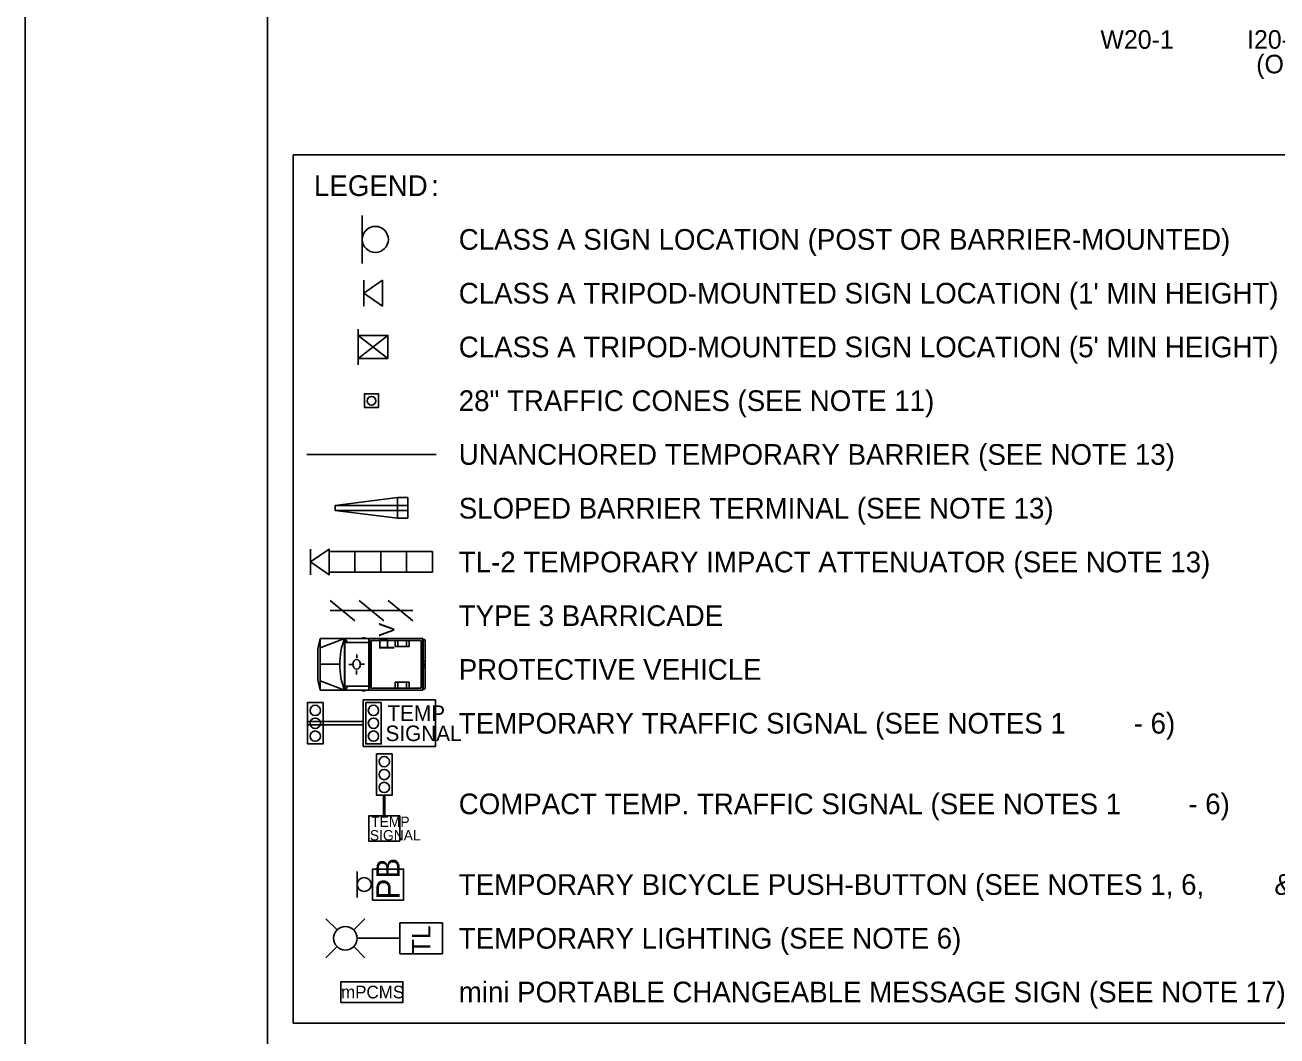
# Model space of a CAD drawing. Extents: x 99976 to 100136, y 99905 to 100011.
# Drawn here: x 99999.062 to 100003.905, y 99911.176 to 99915.088 of the extents above; entities that cross this region are included whole.
import ezdxf

# ---------------------------------------------------------------- set-up
doc = ezdxf.new("R2010")
doc.units = 0
for name, color, linetype in [('SH_GI_PlotLimits', 7, 'Continuous'), ('SH_GI_SheetBorder', 7, 'Continuous'), ('TR_SN_ConstructionSigns', 7, 'Continuous'), ('TR_WZ_BarricadeType3', 7, 'Continuous'), ('TR_WZ_BarrierTemp', 7, 'Continuous'), ('TR_WZ_PortableChangeMessageSign', 7, 'Continuous'), ('TR_WZ_PortableLightStandard', 7, 'Continuous'), ('TR_WZ_PortableSignMount5ftMinBlk-Wht', 7, 'Continuous'), ('TR_WZ_PortableSignMountBlk-Wht', 7, 'Continuous'), ('TR_WZ_ProtectiveVehicle', 7, 'Continuous'), ('TR_WZ_ScaleTerminalEndSection', 7, 'Continuous'), ('TR_WZ_Sign', 7, 'Continuous'), ('TR_WZ_TempSignal', 7, 'Continuous'), ('TR_WZ_TrafficCone', 7, 'Continuous'), ('TR_WZ_WorkZoneDetails', 7, 'Continuous'), ('TR_WZ_WorkZoneTextCurrent', 7, 'Continuous')]:
    doc.layers.add(name, color=color, linetype=linetype)

msp = doc.modelspace()

# ---------------------------------------------------------------- linework, layer by layer
at = {"layer": 'SH_GI_PlotLimits'}
msp.add_lwpolyline([(99999.0625, 99909.6875), (100016.0625, 99909.6875), (100016.0625, 99920.6875), (99999.0625, 99920.6875)], close=True, dxfattribs=at)
at = {"layer": 'SH_GI_SheetBorder'}
msp.add_line((100000, 99920.375), (100000, 99910), dxfattribs=at)
at = {"layer": 'TR_WZ_BarricadeType3'}
for p, q in [((100000.3381, 99912.7823), (100000.2425, 99912.8615)), ((100000.4503, 99912.7823), (100000.3547, 99912.8615)), ((100000.5625, 99912.7823), (100000.4669, 99912.8615)), ((100000.2425, 99912.8219), (100000.5625, 99912.8219))]:
    msp.add_line(p, q, dxfattribs=at)
at = {"layer": 'TR_WZ_BarrierTemp'}
msp.add_line((100000.1525, 99913.4259), (100000.6525, 99913.4259), dxfattribs=at)
at = {"layer": 'TR_WZ_PortableChangeMessageSign'}
msp.add_lwpolyline([(100000.2841, 99911.3059), (100000.5241, 99911.3059), (100000.5241, 99911.3859), (100000.2841, 99911.3859)], close=True, dxfattribs=at)
msp.add_lwpolyline([(100000.2841, 99911.3059), (100000.5241, 99911.3059), (100000.5241, 99911.3859), (100000.2841, 99911.3859), (100000.2841, 99911.3059)], dxfattribs=at)
at = {"layer": 'TR_WZ_PortableLightStandard'}
for p, q in [((100000.2692, 99911.5863), (100000.2261, 99911.6293)), ((100000.3339, 99911.5863), (100000.377, 99911.6293)), ((100000.6777, 99911.6139), (100000.5117, 99911.6139)), ((100000.5117, 99911.6139), (100000.5117, 99911.4939)), ((100000.6777, 99911.6139), (100000.5117, 99911.6139)), ((100000.6777, 99911.6139), (100000.6777, 99911.4939)), ((100000.5117, 99911.5539), (100000.3473, 99911.5539)), ((100000.2692, 99911.5215), (100000.2261, 99911.4784)), ((100000.3339, 99911.5215), (100000.377, 99911.4784)), ((100000.6777, 99911.4939), (100000.5117, 99911.4939)), ((100000.5117, 99911.4939), (100000.6777, 99911.4939))]:
    msp.add_line(p, q, dxfattribs=at)
for points in [[(100000.5117, 99911.6139), (100000.5117, 99911.5539), (100000.5117, 99911.4939)], [(100000.6777, 99911.4939), (100000.6777, 99911.5539), (100000.6777, 99911.6139)]]:
    msp.add_lwpolyline(points, dxfattribs=at)
msp.add_circle((100000.3015, 99911.5539), 0.0457, dxfattribs=at)
msp.add_circle((100000.3015, 99911.5539), 0.0457, dxfattribs=at)
at = {"layer": 'TR_WZ_PortableSignMount5ftMinBlk-Wht'}
for p, q in [((100000.3512, 99913.9109), (100000.3512, 99913.7729)), ((100000.4663, 99913.7971), (100000.3512, 99913.8867)), ((100000.4663, 99913.8867), (100000.3512, 99913.7971)), ((100000.4088, 99913.8419), (100000.4088, 99913.8419)), ((100000.4089, 99913.8418), (100000.4089, 99913.8418))]:
    msp.add_line(p, q, dxfattribs=at)
msp.add_lwpolyline([(100000.4663, 99913.7971), (100000.4663, 99913.8867), (100000.3512, 99913.8867), (100000.3512, 99913.7971)], close=True, dxfattribs=at)
at = {"layer": 'TR_WZ_PortableSignMountBlk-Wht'}
for p, q in [((100000.3728, 99913.9999), (100000.3728, 99914.0999)), ((100000.1667, 99913.0599), (100000.1667, 99912.9599))]:
    msp.add_line(p, q, dxfattribs=at)
for points in [[(100000.3728, 99914.0498), (100000.4447, 99914.0999), (100000.4447, 99913.9999)], [(100000.1667, 99913.01), (100000.2385, 99912.9599), (100000.2385, 99913.0599)]]:
    msp.add_lwpolyline(points, close=True, dxfattribs=at)
at = {"layer": 'TR_WZ_ProtectiveVehicle'}
for p, q in [((100000.2036, 99912.7139), (100000.1944, 99912.6735)), ((100000.2036, 99912.5139), (100000.2036, 99912.7139)), ((100000.2036, 99912.7139), (100000.3925, 99912.7139)), ((100000.2036, 99912.6773), (100000.2981, 99912.7139)), ((100000.2981, 99912.5139), (100000.2981, 99912.7139)), ((100000.2998, 99912.5139), (100000.2998, 99912.7139)), ((100000.3098, 99912.6984), (100000.2998, 99912.7139)), ((100000.2998, 99912.6984), (100000.3925, 99912.6984)), ((100000.3668, 99912.7167), (100000.3781, 99912.7167)), ((100000.3925, 99912.5139), (100000.3925, 99912.7139)), ((100000.601, 99912.7139), (100000.3953, 99912.7139)), ((100000.3953, 99912.5139), (100000.3953, 99912.7139)), ((100000.5952, 99912.7059), (100000.4011, 99912.7059)), ((100000.4011, 99912.5219), (100000.4011, 99912.7059)), ((100000.4938, 99912.7059), (100000.4938, 99912.6829)), ((100000.5038, 99912.7059), (100000.5038, 99912.6829)), ((100000.5378, 99912.7059), (100000.5378, 99912.6829)), ((100000.5488, 99912.7059), (100000.5488, 99912.6829)), ((100000.5952, 99912.5219), (100000.5952, 99912.7059)), ((100000.601, 99912.5139), (100000.601, 99912.7139)), ((100000.6061, 99912.7106), (100000.6017, 99912.7106)), ((100000.6017, 99912.5172), (100000.6017, 99912.7106)), ((100000.6106, 99912.5233), (100000.6106, 99912.7045)), ((100000.1944, 99912.5543), (100000.1944, 99912.6735)), ((100000.3458, 99912.6524), (100000.3455, 99912.6373)), ((100000.5488, 99912.6829), (100000.4938, 99912.6829)), ((100000.2036, 99912.6139), (100000.2795, 99912.6139)), ((100000.315, 99912.6138), (100000.3276, 99912.6138)), ((100000.3592, 99912.6142), (100000.3592, 99912.6142)), ((100000.376, 99912.6147), (100000.3611, 99912.6143)), ((100000.6106, 99912.628), (100000.6017, 99912.6242)), ((100000.6106, 99912.5998), (100000.6017, 99912.6036)), ((100000.6082, 99912.6139), (100000.6041, 99912.6139)), ((100000.6061, 99912.6111), (100000.6061, 99912.6167)), ((100000.2036, 99912.5139), (100000.1944, 99912.5543)), ((100000.2036, 99912.5505), (100000.2981, 99912.5139)), ((100000.3451, 99912.5743), (100000.3451, 99912.5904)), ((100000.2036, 99912.5139), (100000.3925, 99912.5139)), ((100000.2998, 99912.5139), (100000.3118, 99912.5294)), ((100000.2998, 99912.5294), (100000.3925, 99912.5294)), ((100000.3668, 99912.5111), (100000.3781, 99912.5111)), ((100000.601, 99912.5139), (100000.3953, 99912.5139)), ((100000.5952, 99912.5219), (100000.4011, 99912.5219)), ((100000.5488, 99912.5449), (100000.4938, 99912.5449)), ((100000.4938, 99912.5219), (100000.4938, 99912.5449)), ((100000.5038, 99912.5219), (100000.5038, 99912.5449)), ((100000.5378, 99912.5219), (100000.5378, 99912.5449)), ((100000.5488, 99912.5219), (100000.5488, 99912.5449)), ((100000.6061, 99912.5172), (100000.6017, 99912.5172))]:
    msp.add_line(p, q, dxfattribs=at)
for centre, major_axis, start_param, end_param in [((100000.4331, 99912.6139), (0, -0.2099), 4.215852, 5.209111), ((100000.6061, 99912.7045), (0, 0.0061), 4.712389, 6.283185), ((100000.6061, 99912.5233), (0, -0.0061), 6.283185, 7.853982)]:
    msp.add_ellipse(centre, major_axis=major_axis, ratio=0.73155, start_param=start_param, end_param=end_param, dxfattribs=at)
for centre, major_axis in [((100000.3451, 99912.6139), (0, 0.0193)), ((100000.6061, 99912.6139), (0, 0.00282))]:
    msp.add_ellipse(centre, major_axis=major_axis, ratio=0.73155, dxfattribs=at)
at = {"layer": 'TR_WZ_ScaleTerminalEndSection'}
for p, q in [((100000.5025, 99913.259), (100000.2625, 99913.229)), ((100000.2625, 99913.229), (100000.5425, 99913.229)), ((100000.2625, 99913.229), (100000.2625, 99913.209)), ((100000.5025, 99913.259), (100000.5025, 99913.179)), ((100000.5425, 99913.259), (100000.5025, 99913.259)), ((100000.5425, 99913.259), (100000.5425, 99913.179)), ((100000.2625, 99913.209), (100000.5425, 99913.209)), ((100000.5025, 99913.179), (100000.2625, 99913.209)), ((100000.5425, 99913.179), (100000.5025, 99913.179))]:
    msp.add_line(p, q, dxfattribs=at)
at = {"layer": 'TR_WZ_Sign'}
for p, q in [((100000.3668, 99914.1647), (100000.3668, 99914.3511)), ((100000.3474, 99911.7119), (100000.3474, 99911.8119))]:
    msp.add_line(p, q, dxfattribs=at)
for centre, radius in [((100000.4172, 99914.258), 0.0504), ((100000.4172, 99914.258), 0.0504), ((100000.3744, 99911.762), 0.027), ((100000.3744, 99911.762), 0.027)]:
    msp.add_circle(centre, radius, dxfattribs=at)
at = {"layer": 'TR_WZ_TempSignal'}
for p, q in [((100000.215, 99912.4658), (100000.1551, 99912.4658)), ((100000.1551, 99912.4658), (100000.1551, 99912.306)), ((100000.215, 99912.306), (100000.215, 99912.4658)), ((100000.3701, 99912.4759), (100000.6501, 99912.4759)), ((100000.3701, 99912.2959), (100000.3701, 99912.4759)), ((100000.6501, 99912.4759), (100000.3701, 99912.4759)), ((100000.3701, 99912.4759), (100000.3701, 99912.3926)), ((100000.44, 99912.4658), (100000.3801, 99912.4658)), ((100000.3801, 99912.4658), (100000.3801, 99912.306)), ((100000.44, 99912.306), (100000.44, 99912.4658)), ((100000.6501, 99912.4759), (100000.6501, 99912.2959)), ((100000.6501, 99912.2959), (100000.6501, 99912.4759)), ((100000.3701, 99912.3926), (100000.1551, 99912.3926)), ((100000.1551, 99912.3926), (100000.1551, 99912.3792)), ((100000.1551, 99912.3792), (100000.3701, 99912.3792)), ((100000.3701, 99912.3792), (100000.3701, 99912.3926)), ((100000.3701, 99912.3926), (100000.3701, 99912.3792)), ((100000.3701, 99912.3792), (100000.3701, 99912.2959)), ((100000.1551, 99912.306), (100000.215, 99912.306)), ((100000.6501, 99912.2959), (100000.3701, 99912.2959)), ((100000.3701, 99912.2959), (100000.6501, 99912.2959)), ((100000.3801, 99912.306), (100000.44, 99912.306)), ((100000.4819, 99912.2672), (100000.422, 99912.2672)), ((100000.422, 99912.2672), (100000.422, 99912.1075)), ((100000.4819, 99912.1075), (100000.4819, 99912.2672)), ((100000.422, 99912.1075), (100000.4819, 99912.1075)), ((100000.5119, 99912.0275), (100000.3919, 99912.0275)), ((100000.3919, 99912.0275), (100000.3919, 99911.983)), ((100000.5119, 99911.9297), (100000.5119, 99912.0275)), ((100000.3919, 99911.983), (100000.3919, 99911.9742)), ((100000.3919, 99911.9742), (100000.3919, 99911.9297)), ((100000.3919, 99911.9297), (100000.5119, 99911.9297))]:
    msp.add_line(p, q, dxfattribs=at)
for points in [[(100000.215, 99912.4658), (100000.1551, 99912.4658), (100000.1551, 99912.306), (100000.215, 99912.306), (100000.215, 99912.4658)], [(100000.44, 99912.4658), (100000.3801, 99912.4658), (100000.3801, 99912.306), (100000.44, 99912.306), (100000.44, 99912.4658)], [(100000.4819, 99912.2672), (100000.422, 99912.2672), (100000.422, 99912.1075), (100000.4819, 99912.1075), (100000.4819, 99912.2672)], [(100000.5119, 99912.0275), (100000.3919, 99912.0275), (100000.3919, 99911.9297), (100000.5119, 99911.9297), (100000.5119, 99912.0275)]]:
    msp.add_lwpolyline(points, dxfattribs=at)
for points in [[(100000.4494, 99912.1075), (100000.4544, 99912.1075), (100000.4544, 99912.0275), (100000.4494, 99912.0275)], [(100000.4064, 99911.7019), (100000.4064, 99911.8219), (100000.5264, 99911.8219), (100000.5264, 99911.7019)], [(100000.4064, 99911.7019), (100000.4064, 99911.8219), (100000.5264, 99911.8219), (100000.5264, 99911.7019)]]:
    msp.add_lwpolyline(points, close=True, dxfattribs=at)
for centre in [(100000.1851, 99912.4358), (100000.1851, 99912.4358), (100000.4101, 99912.4358), (100000.4101, 99912.4358), (100000.1851, 99912.3859), (100000.1851, 99912.3859), (100000.4101, 99912.3859), (100000.4101, 99912.3859), (100000.1851, 99912.336), (100000.1851, 99912.336), (100000.4101, 99912.336), (100000.4101, 99912.336), (100000.4519, 99912.2373), (100000.4519, 99912.2373), (100000.4519, 99912.1874), (100000.4519, 99912.1874), (100000.4519, 99912.1374), (100000.4519, 99912.1374)]:
    msp.add_circle(centre, 0.02, dxfattribs=at)
at = {"layer": 'TR_WZ_TrafficCone'}
for points in [[(100000.3759, 99913.6606), (100000.4293, 99913.6606), (100000.4293, 99913.6072), (100000.3759, 99913.6072), (100000.3759, 99913.6606)], [(100000.3759, 99913.6072), (100000.4293, 99913.6072), (100000.4293, 99913.6606), (100000.3759, 99913.6606), (100000.3759, 99913.6072)]]:
    msp.add_lwpolyline(points, dxfattribs=at)
msp.add_circle((100000.4026, 99913.6339), 0.0167, dxfattribs=at)
at = {"layer": 'TR_WZ_WorkZoneDetails'}
for p, q in [((100000.6385, 99913.0499), (100000.2385, 99913.0499)), ((100000.2385, 99913.0499), (100000.6385, 99913.0499)), ((100000.2385, 99912.9699), (100000.2385, 99913.0499)), ((100000.3385, 99913.0499), (100000.3385, 99912.9699)), ((100000.4385, 99913.0499), (100000.4385, 99912.9699)), ((100000.5385, 99913.0499), (100000.5385, 99912.9699)), ((100000.6385, 99913.0499), (100000.6385, 99912.9699)), ((100000.6385, 99912.9699), (100000.6385, 99913.0499)), ((100000.6385, 99912.9699), (100000.2385, 99912.9699)), ((100000.6385, 99912.9699), (100000.2385, 99912.9699))]:
    msp.add_line(p, q, dxfattribs=at)
msp.add_lwpolyline([(100000.4447, 99913.9999), (100000.4447, 99914.0999), (100000.3728, 99914.0498), (100000.4447, 99913.9999)], dxfattribs=at)
at = {"layer": 'TR_WZ_WorkZoneTextCurrent'}
msp.add_lwpolyline([(100000.1, 99914.5859), (100004.1384, 99914.5859), (100004.1384, 99911.2259), (100000.1, 99911.2259)], close=True, dxfattribs=at)

# ---------------------------------------------------------------- texts
at = {"layer": 'TR_SN_ConstructionSigns'}
for s, p in [('W20-1', (100003.2217, 99914.9956)), ('I20-301 (B/W)', (100003.7889, 99914.9956)), ('(OPTIONAL)', (100003.8244, 99914.9005))]:
    msp.add_text(s, height=0.072, rotation=360, dxfattribs=at).set_placement(p)
at = {"layer": 'TR_WZ_PortableChangeMessageSign'}
msp.add_text('mPCMS', height=0.04909, rotation=360, dxfattribs=at).set_placement((100000.2845, 99911.3214))
at = {"layer": 'TR_WZ_PortableLightStandard'}
msp.add_text('TL', height=0.07, rotation=90, dxfattribs=at).set_placement((100000.6297, 99911.4937))
at = {"layer": 'TR_WZ_ProtectiveVehicle'}
msp.add_text('PV', height=0.06, rotation=90, dxfattribs=at).set_placement((100000.4913, 99912.6677))
at = {"layer": 'TR_WZ_TempSignal'}
for s, height, p in [('TEMP', 0.06, (100000.4641, 99912.3949)), ('SIGNAL', 0.06, (100000.4567, 99912.3169)), ('TEMP', 0.04, (100000.4013, 99911.9846)), ('SIGNAL', 0.04, (100000.3963, 99911.9326))]:
    msp.add_text(s, height=height, dxfattribs=at).set_placement(p)
msp.add_text('PB', height=0.09, rotation=90, dxfattribs=at).set_placement((100000.5114, 99911.7042))
at = {"layer": 'TR_WZ_WorkZoneTextCurrent'}
for s, p in [('LEGEND', (100000.18, 99914.4259)), (':', (100000.6328, 99914.4259)), ('CLASS A SIGN LOCATION (POST OR BARRIER-MOUNTED)', (100000.74, 99914.2179)), ("CLASS A TRIPOD-MOUNTED SIGN LOCATION (1' MIN HEIGHT)", (100000.74, 99914.0099)), ("CLASS A TRIPOD-MOUNTED SIGN LOCATION (5' MIN HEIGHT)", (100000.74, 99913.8019)), ('28" TRAFFIC CONES (SEE NOTE 11)', (100000.74, 99913.5939)), ('UNANCHORED TEMPORARY BARRIER (SEE NOTE 13)', (100000.74, 99913.3859)), ('SLOPED BARRIER TERMINAL (SEE NOTE 13)', (100000.74, 99913.1779)), ('TL-2 TEMPORARY IMPACT ATTENUATOR (SEE NOTE 13)', (100000.74, 99912.9699)), ('TYPE 3 BARRICADE', (100000.74, 99912.7619)), ('PROTECTIVE VEHICLE', (100000.74, 99912.5539)), ('TEMPORARY TRAFFIC SIGNAL (SEE NOTES 1', (100000.74, 99912.3459)), ('- 6)', (100003.3504, 99912.3459)), ('COMPACT TEMP. TRAFFIC SIGNAL (SEE NOTES 1', (100000.74, 99912.0339)), ('- 6)', (100003.5616, 99912.0339)), ('TEMPORARY BICYCLE PUSH-BUTTON (SEE NOTES 1, 6,', (100000.74, 99911.7219)), ('&', (100003.8945, 99911.7219)), ('TEMPORARY LIGHTING (SEE NOTE 6)', (100000.74, 99911.5139)), ('mini PORTABLE CHANGEABLE MESSAGE SIGN (SEE NOTE 17)', (100000.74, 99911.3059))]:
    msp.add_text(s, height=0.08, rotation=360, dxfattribs=at).set_placement(p)

doc.saveas('drawing.dxf')
